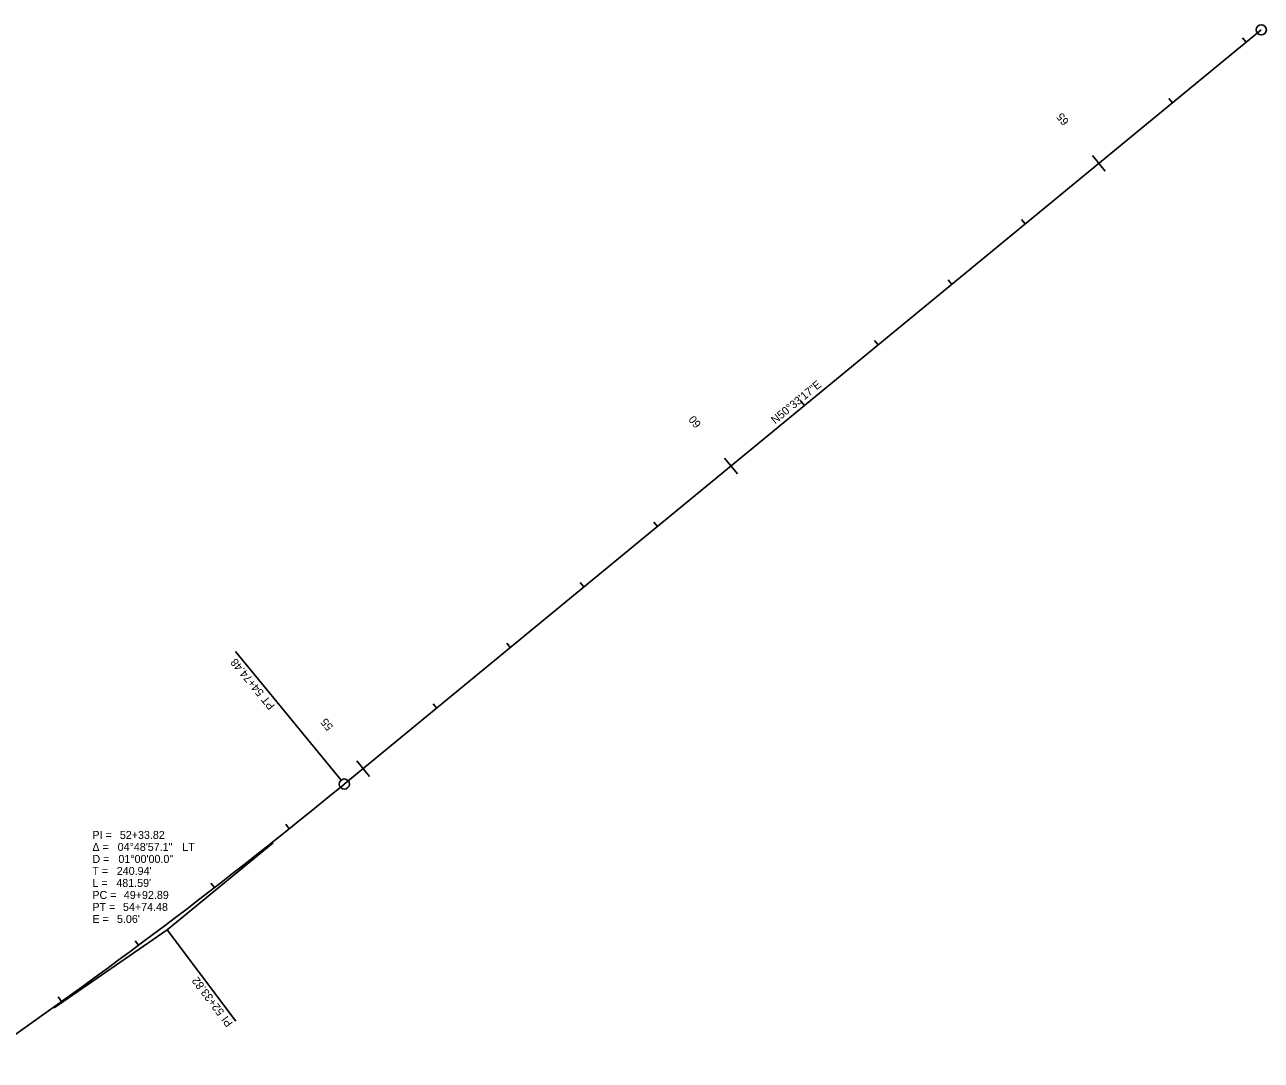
# Model space of a CAD drawing. Extents: x 1145421 to 1155673, y 2015317 to 2021442.
# Drawn here: x 1148342 to 1149640, y 2018027 to 2019114 of the extents above; entities that cross this region are included whole.
import ezdxf

# ---------------------------------------------------------------- set-up
doc = ezdxf.new("R2010")
doc.units = 0
for name, color, linetype in [('Default', 7, 'Continuous'), ('EX_CONTOUR_ANNOT_MINOR', 7, 'Continuous'), ('EX_TERRAIN', 7, 'Continuous')]:
    doc.layers.add(name, color=color, linetype=linetype)

msp = doc.modelspace()

# ---------------------------------------------------------------- linework, layer by layer
at = {"layer": 'Default'}
msp.add_line((1148677.5, 2018316.5), (1149639.9, 2019108.3), dxfattribs=at)
msp.add_arc((1145037.3, 2022741.1), 5729.6, 304.62946, 309.44534, dxfattribs=at)
at = {"layer": 'EX_CONTOUR_ANNOT_MINOR'}
for p, q in [((1149620.1, 2019099.8), (1149623.9, 2019095.2)), ((1149542.9, 2019036.3), (1149546.7, 2019031.6)), ((1149462.7, 2018976.3), (1149476.2, 2018959.9)), ((1149388.4, 2018909.2), (1149392.2, 2018904.6)), ((1149311.2, 2018845.7), (1149315, 2018841)), ((1149234, 2018782.1), (1149237.8, 2018777.5)), ((1149156.8, 2018718.6), (1149160.6, 2018714)), ((1149076.6, 2018658.7), (1149090.1, 2018642.3)), ((1149002.3, 2018591.5), (1149006.1, 2018586.9)), ((1148925.1, 2018528), (1148928.9, 2018523.4)), ((1148847.9, 2018464.5), (1148851.7, 2018459.8)), ((1148674.1, 2018320.7), (1148563.2, 2018455.5)), ((1148563.2, 2018455.5), (1148563.2, 2018455.5)), ((1148770.7, 2018400.9), (1148774.5, 2018396.3)), ((1148690.5, 2018341), (1148703.9, 2018324.6)), ((1148677.5, 2018316.5), (1148677.5, 2018316.5)), ((1148616, 2018274.3), (1148619.7, 2018269.6)), ((1148491.5, 2018163.5), (1148602.7, 2018254.9)), ((1148537.5, 2018212.5), (1148541.1, 2018207.8)), ((1148491.5, 2018163.5), (1148373, 2018081.6)), ((1148491.5, 2018163.5), (1148563.8, 2018067.7)), ((1148457.9, 2018152.1), (1148461.5, 2018147.3)), ((1148377.3, 2018093.1), (1148380.8, 2018088.2)), ((1148563.8, 2018067.7), (1148563.8, 2018067.7))]:
    msp.add_line(p, q, dxfattribs=at)
for centre in [(1149639.9, 2019108.3), (1148677.5, 2018316.5)]:
    msp.add_circle(centre, 5.34, dxfattribs=at)
at = {"layer": 'EX_TERRAIN'}
msp.add_line((1148677.5, 2018316.5), (1149639.9, 2019108.3), dxfattribs=at)
msp.add_arc((1145037.3, 2022741.1), 5729.6, 304.62946, 309.44534, dxfattribs=at)

# ---------------------------------------------------------------- texts
at = {"layer": 'EX_CONTOUR_ANNOT_MINOR'}
for s, rotation, p in [('65', 129.4453, (1149438.6, 2019012.3)), ('N50°33\'17"E', 39.4453, (1149129.7, 2018694)), ('60', 129.4453, (1149052.5, 2018694.5)), ('54+74.48', 129.4453, (1148593.7, 2018412.8)), ('PT', 129.4453, (1148605.2, 2018398.8)), ('55', 129.4453, (1148666.3, 2018376.9)), ('52+33.82', 127.0374, (1148552, 2018077.3)), ('PI ', 127.0374, (1148560.9, 2018065.5))]:
    msp.add_text(s, height=8.4, rotation=rotation, dxfattribs=at).set_placement(p)
for s, p in [('PI = ', (1148413.1, 2018258.9)), ('52+33.82', (1148441.9, 2018258.9)), ('Δ = ', (1148413.1, 2018246.3)), ('04°48\'57.1"', (1148439.6, 2018246.3)), (' LT', (1148504.3, 2018246.3)), ('D = ', (1148413.1, 2018233.7)), ('01°00\'00.0"', (1148440.4, 2018233.7)), ('T = ', (1148413.1, 2018221.1)), ("240.94'", (1148438.7, 2018221.1)), ('L = ', (1148413.1, 2018208.5)), ("481.59'", (1148438.2, 2018208.5)), ('PC = ', (1148413.1, 2018195.9)), ('49+92.89', (1148446.1, 2018195.9)), ('PT = ', (1148413.1, 2018183.3)), ('54+74.48', (1148445.2, 2018183.3)), ('E = ', (1148413.1, 2018170.7)), ("5.06'", (1148438.9, 2018170.7))]:
    msp.add_text(s, height=8.4, dxfattribs=at).set_placement(p)

doc.saveas('drawing.dxf')
